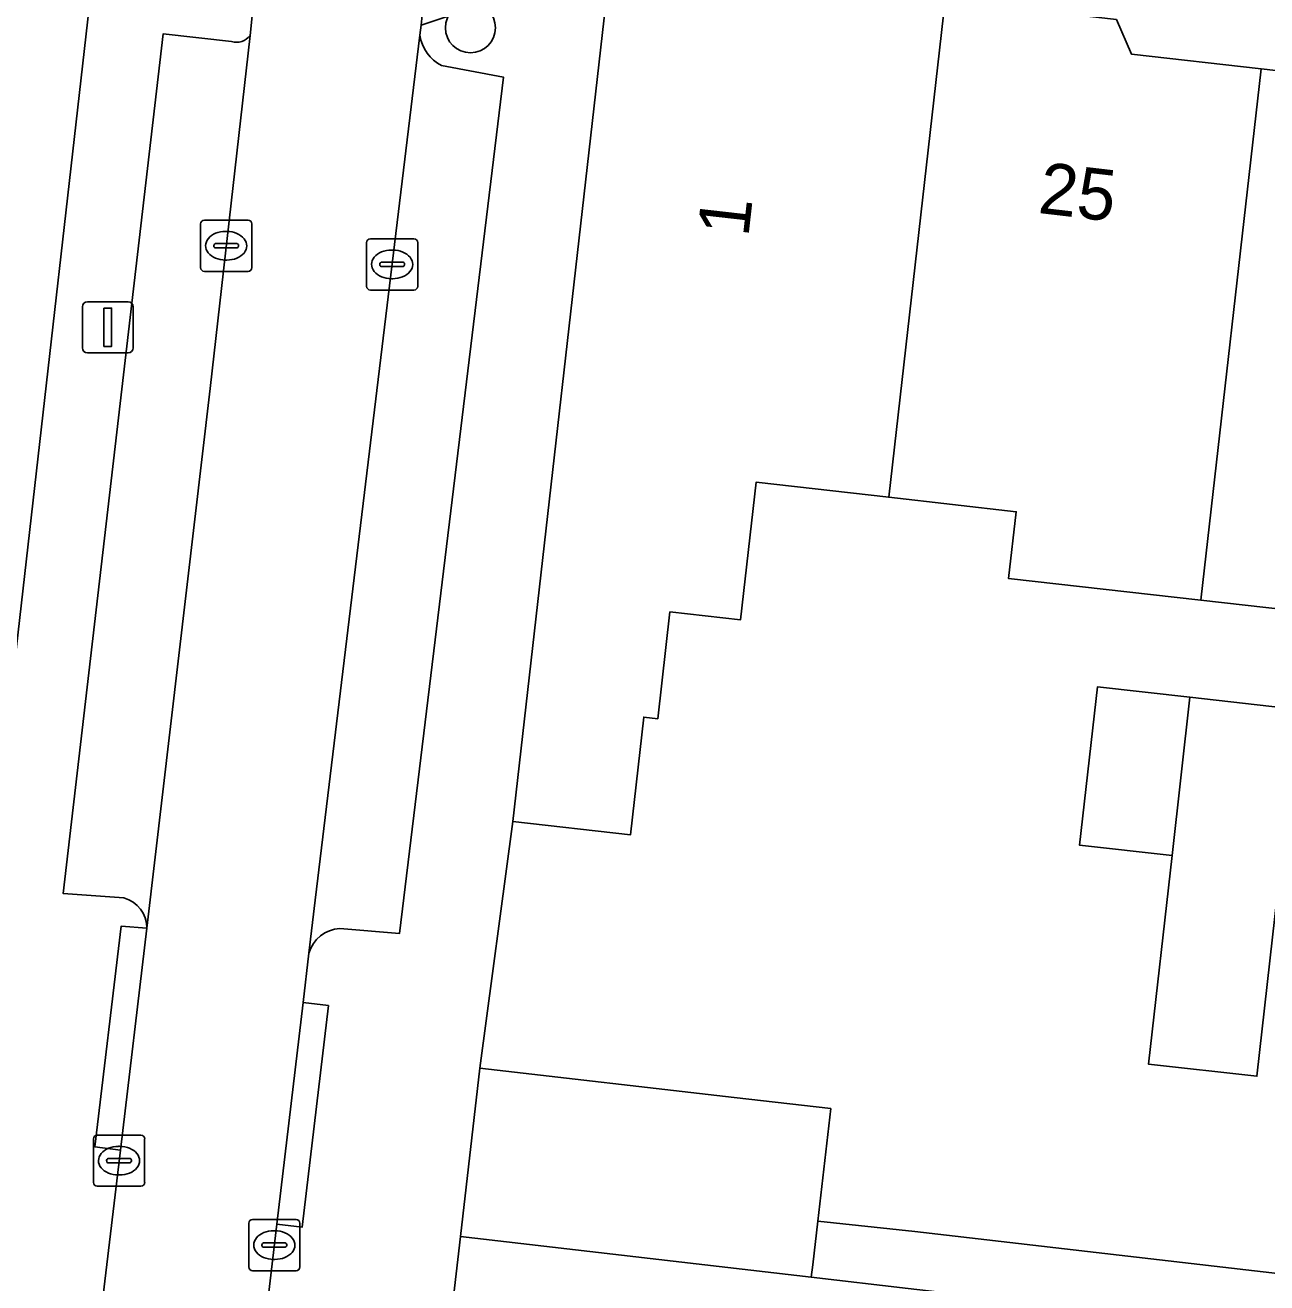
# Model space of a CAD drawing. Extents: x 161692 to 162379, y 380760 to 381678.
# Drawn here: x 162087.29 to 162111.53, y 381116.36 to 381140.92 of the extents above; entities that cross this region are included whole.
import ezdxf

# ---------------------------------------------------------------- set-up
doc = ezdxf.new("R2010")
doc.units = 0
for name, color, linetype in [('IMGEO_Boom', 7, 'Continuous'), ('IMGEO_Erf', 7, 'Continuous'), ('IMGEO_Kolk', 7, 'Continuous'), ('IMGEO_Lichtmast', 7, 'Continuous'), ('IMGEO_Muur', 7, 'Continuous'), ('IMGEO_Pand', 7, 'Continuous'), ('IMGEO_Pand_nummerreeks', 7, 'Continuous'), ('IMGEO_Parkeervlak_open', 7, 'Continuous'), ('IMGEO_Rijbaan_lokaal_open', 7, 'Continuous'), ('IMGEO_Voetpad_open', 7, 'Continuous')]:
    doc.layers.add(name, color=color, linetype=linetype)

msp = doc.modelspace()

# ---------------------------------------------------------------- linework, layer by layer
at = {"layer": 'IMGEO_Boom'}
msp.add_circle((162095.978, 381140.866), 0.489, dxfattribs=at)
at = {"layer": 'IMGEO_Erf'}
msp.add_lwpolyline([(162114.163, 381129.244), (162110.241, 381129.686), (162106.484, 381130.11), (162106.633, 381131.414), (162104.145, 381131.697), (162101.554, 381131.991), (162101.248, 381129.301), (162099.872, 381129.457), (162099.635, 381127.373), (162099.363, 381127.404), (162099.102, 381125.102), (162096.806, 381125.362), (162096.163, 381120.55), (162101.13, 381119.976), (162103.013, 381119.759), (162102.759, 381117.558), (162104.656, 381117.359), (162150.568, 381112.043)], dxfattribs=at)
msp.add_lwpolyline([(162109.675, 381124.698), (162107.87, 381124.902), (162108.218, 381127.994), (162110.026, 381127.79), (162112.139, 381127.552), (162111.332, 381120.389), (162109.214, 381120.628)], close=True, dxfattribs=at)
at = {"layer": 'IMGEO_Kolk'}
for p, q in [((162090.784, 381137.108), (162091.636, 381137.108)), ((162090.709, 381136.182), (162090.709, 381137.034)), ((162091.197, 381136.888), (162091.222, 381136.888)), ((162091.71, 381137.034), (162091.71, 381136.182)), ((162090.968, 381136.602), (162090.968, 381136.614)), ((162091.011, 381136.651), (162091.409, 381136.651)), ((162091.452, 381136.614), (162091.452, 381136.602)), ((162093.949, 381135.818), (162093.949, 381136.67)), ((162094.024, 381136.744), (162094.876, 381136.744)), ((162094.95, 381136.67), (162094.95, 381135.818)), ((162091.406, 381136.565), (162091.008, 381136.565)), ((162091.22, 381136.328), (162091.195, 381136.328)), ((162094.437, 381136.524), (162094.462, 381136.524)), ((162091.636, 381136.108), (162090.784, 381136.108)), ((162094.208, 381136.238), (162094.208, 381136.25)), ((162094.646, 381136.201), (162094.248, 381136.201)), ((162094.251, 381136.287), (162094.649, 381136.287)), ((162094.692, 381136.25), (162094.692, 381136.238)), ((162094.46, 381135.964), (162094.435, 381135.964)), ((162094.876, 381135.744), (162094.024, 381135.744)), ((162088.617, 381118.316), (162088.617, 381119.168)), ((162088.692, 381119.242), (162089.544, 381119.242)), ((162089.618, 381119.168), (162089.618, 381118.316)), ((162089.105, 381119.022), (162089.13, 381119.022)), ((162088.876, 381118.736), (162088.876, 381118.748)), ((162089.314, 381118.699), (162088.916, 381118.699)), ((162088.919, 381118.785), (162089.317, 381118.785)), ((162089.36, 381118.748), (162089.36, 381118.736)), ((162089.128, 381118.462), (162089.103, 381118.462)), ((162089.544, 381118.242), (162088.692, 381118.242)), ((162091.649, 381116.667), (162091.649, 381117.519)), ((162091.724, 381117.593), (162092.576, 381117.593)), ((162092.65, 381117.519), (162092.65, 381116.667)), ((162092.137, 381117.373), (162092.162, 381117.373)), ((162091.908, 381117.087), (162091.908, 381117.099)), ((162092.346, 381117.05), (162091.948, 381117.05)), ((162091.951, 381117.136), (162092.349, 381117.136)), ((162092.392, 381117.099), (162092.392, 381117.087)), ((162092.16, 381116.813), (162092.135, 381116.813)), ((162092.576, 381116.593), (162091.724, 381116.593))]:
    msp.add_line(p, q, dxfattribs=at)
for points in [[(162090.784, 381137.108), (162091.636, 381137.108)], [(162090.709, 381136.182), (162090.709, 381137.034)], [(162091.71, 381137.034), (162091.71, 381136.182)], [(162093.949, 381135.818), (162093.949, 381136.67)], [(162094.024, 381136.744), (162094.876, 381136.744)], [(162094.95, 381136.67), (162094.95, 381135.818)], [(162091.636, 381136.108), (162090.784, 381136.108)], [(162094.876, 381135.744), (162094.024, 381135.744)], [(162088.617, 381118.316), (162088.617, 381119.168)], [(162088.692, 381119.242), (162089.544, 381119.242)], [(162089.618, 381119.168), (162089.618, 381118.316)], [(162089.544, 381118.242), (162088.692, 381118.242)], [(162091.649, 381116.667), (162091.649, 381117.519)], [(162091.724, 381117.593), (162092.576, 381117.593)], [(162092.65, 381117.519), (162092.65, 381116.667)], [(162092.576, 381116.593), (162091.724, 381116.593)]]:
    msp.add_lwpolyline(points, dxfattribs=at)
for centre, radius, start, end in [((162090.786, 381137.032), 0.0765, 91.552, 178.448), ((162090.786, 381137.032), 0.0765, 91.552, 178.448), ((162091.634, 381137.032), 0.0765, 1.552, 88.448), ((162091.634, 381137.032), 0.0765, 1.552, 88.448), ((162091.008, 381136.611), 0.0403, 85.8775, 175.7526), ((162091.005, 381136.601), 0.0366, 178.938, 274.7102), ((162091.409, 381136.608), 0.043, 264.8664, 352.4533), ((162091.413, 381136.613), 0.0386, 1.7309, 96.639), ((162094.026, 381136.668), 0.0765, 91.552, 178.448), ((162094.026, 381136.668), 0.0765, 91.552, 178.448), ((162094.874, 381136.668), 0.0765, 1.552, 88.448), ((162094.874, 381136.668), 0.0765, 1.552, 88.448), ((162090.786, 381136.184), 0.0765, 181.552, 268.448), ((162090.786, 381136.184), 0.0765, 181.552, 268.448), ((162091.634, 381136.184), 0.0765, 271.552, 358.448), ((162091.634, 381136.184), 0.0765, 271.552, 358.448), ((162094.248, 381136.247), 0.0403, 85.8775, 175.7526), ((162094.245, 381136.237), 0.0366, 178.938, 274.7102), ((162094.649, 381136.244), 0.043, 264.8664, 352.4533), ((162094.653, 381136.249), 0.0386, 1.7309, 96.639), ((162094.026, 381135.82), 0.0765, 181.552, 268.448), ((162094.026, 381135.82), 0.0765, 181.552, 268.448), ((162094.874, 381135.82), 0.0765, 271.552, 358.448), ((162094.874, 381135.82), 0.0765, 271.552, 358.448), ((162088.694, 381119.166), 0.0765, 91.552, 178.448), ((162088.694, 381119.166), 0.0765, 91.552, 178.448), ((162089.542, 381119.166), 0.0765, 1.552, 88.448), ((162089.542, 381119.166), 0.0765, 1.552, 88.448), ((162088.916, 381118.745), 0.0403, 85.8775, 175.7526), ((162088.913, 381118.735), 0.0366, 178.938, 274.7102), ((162089.317, 381118.742), 0.043, 264.8664, 352.4533), ((162089.321, 381118.747), 0.0386, 1.7309, 96.639), ((162088.694, 381118.318), 0.0765, 181.552, 268.448), ((162088.694, 381118.318), 0.0765, 181.552, 268.448), ((162089.542, 381118.318), 0.0765, 271.552, 358.448), ((162089.542, 381118.318), 0.0765, 271.552, 358.448), ((162091.726, 381117.517), 0.0765, 91.552, 178.448), ((162091.726, 381117.517), 0.0765, 91.552, 178.448), ((162092.574, 381117.517), 0.0765, 1.552, 88.448), ((162092.574, 381117.517), 0.0765, 1.552, 88.448), ((162091.948, 381117.096), 0.0403, 85.8775, 175.7526), ((162091.945, 381117.086), 0.0366, 178.938, 274.7102), ((162092.349, 381117.093), 0.043, 264.8664, 352.4533), ((162092.353, 381117.098), 0.0386, 1.7309, 96.639), ((162091.726, 381116.669), 0.0765, 181.552, 268.448), ((162091.726, 381116.669), 0.0765, 181.552, 268.448), ((162092.574, 381116.669), 0.0765, 271.552, 358.448), ((162092.574, 381116.669), 0.0765, 271.552, 358.448)]:
    msp.add_arc(centre, radius, start, end, dxfattribs=at)
for centre, major_axis, ratio, start_param, end_param in [((162091.196, 381136.608), (-0.387, 0.002), 0.722429, 4.712389, 7.853982), ((162091.221, 381136.608), (-0.39, 0.002), 0.717154, 1.570796, 4.712389), ((162094.436, 381136.244), (-0.387, 0.002), 0.722429, 4.712389, 7.853982), ((162094.461, 381136.244), (-0.39, 0.002), 0.717154, 1.570796, 4.712389), ((162089.104, 381118.742), (-0.387, 0.002), 0.722429, 4.712389, 7.853982), ((162089.129, 381118.742), (-0.39, 0.002), 0.717154, 1.570796, 4.712389), ((162092.136, 381117.093), (-0.387, 0.002), 0.722429, 4.712389, 7.853982), ((162092.161, 381117.093), (-0.39, 0.002), 0.717154, 1.570796, 4.712389)]:
    msp.add_ellipse(centre, major_axis=major_axis, ratio=ratio, start_param=start_param, end_param=end_param, dxfattribs=at)
at = {"layer": 'IMGEO_Lichtmast'}
for p, q in [((162088.403, 381134.616), (162088.403, 381135.416)), ((162088.403, 381135.416), (162088.403, 381134.616)), ((162088.503, 381135.516), (162089.293, 381135.516)), ((162089.293, 381135.516), (162088.503, 381135.516)), ((162089.393, 381135.416), (162089.393, 381134.616)), ((162089.393, 381134.616), (162089.393, 381135.416)), ((162089.293, 381134.516), (162088.503, 381134.516)), ((162088.503, 381134.516), (162089.293, 381134.516))]:
    msp.add_line(p, q, dxfattribs=at)
msp.add_lwpolyline([(162088.823, 381135.391), (162088.973, 381135.391), (162088.973, 381134.641), (162088.823, 381134.641), (162088.823, 381135.391)], dxfattribs=at)
for centre, start, end in [((162088.503, 381135.416), 90, 180), ((162088.503, 381135.416), 90, 180), ((162089.293, 381135.416), 0, 90), ((162089.293, 381135.416), 360, 90), ((162088.503, 381134.616), 180, 270), ((162088.503, 381134.616), 180, 270), ((162089.293, 381134.616), 270, 0), ((162089.293, 381134.616), 270, 0)]:
    msp.add_arc(centre, 0.1, start, end, dxfattribs=at)
at = {"layer": 'IMGEO_Muur'}
msp.add_lwpolyline([(162096.806, 381125.362), (162096.163, 381120.55)], dxfattribs=at)
at = {"layer": 'IMGEO_Pand'}
for points in [[(162081.935, 381144.049), (162080.779, 381134.286), (162080.655, 381133.357), (162083.55, 381133.042), (162083.371, 381131.369), (162084.693, 381131.219), (162084.45, 381129.08), (162087.113, 381128.778), (162088.76, 381143.274)], [(162105.246, 381141.408), (162098.713, 381142.15), (162096.806, 381125.362), (162099.102, 381125.102), (162099.363, 381127.404), (162099.635, 381127.373), (162099.872, 381129.457), (162101.248, 381129.301), (162101.554, 381131.991), (162104.145, 381131.697)], [(162105.246, 381141.408), (162104.145, 381131.697), (162106.633, 381131.414), (162106.484, 381130.11), (162110.241, 381129.686), (162111.418, 381140.063), (162108.883, 381140.351), (162108.589, 381141.028)], [(162117.619, 381139.339), (162117.069, 381139.402), (162116.786, 381140.052), (162114.638, 381140.296), (162114.23, 381139.744), (162111.418, 381140.063), (162110.241, 381129.686), (162114.163, 381129.244), (162114.308, 381130.511), (162116.589, 381130.252)], [(162110.026, 381127.79), (162108.218, 381127.994), (162107.87, 381124.902), (162109.675, 381124.698)], [(162110.026, 381127.79), (162109.675, 381124.698), (162109.214, 381120.628), (162111.332, 381120.389), (162112.139, 381127.552)], [(162103.013, 381119.759), (162101.13, 381119.976), (162096.163, 381120.55), (162095.782, 381117.258), (162102.633, 381116.465), (162102.661, 381116.71), (162102.759, 381117.558)], [(162104.527, 381116.246), (162102.633, 381116.465), (162095.782, 381117.258), (162095.141, 381111.709), (162109.163, 381110.087), (162109.187, 381110.297), (162110.97, 381110.09), (162111.216, 381112.206), (162109.432, 381112.412), (162107.784, 381112.603), (162107.839, 381113.073), (162108.158, 381115.826)]]:
    msp.add_lwpolyline(points, close=True, dxfattribs=at)
at = {"layer": 'IMGEO_Parkeervlak_open'}
for points in [[(162091.313, 381140.596), (162089.979, 381140.744), (162088.03, 381123.957), (162089.211, 381123.872)], [(162089.66, 381123.283), (162090.897, 381133.818), (162091.675, 381140.712)], [(162094.991, 381140.718), (162092.948, 381123.832), (162092.825, 381122.794)], [(162093.427, 381123.276), (162094.596, 381123.179), (162096.621, 381139.903), (162095.414, 381140.127)]]:
    msp.add_lwpolyline(points, dxfattribs=at)
for centre, radius, start, end in [((162091.411, 381140.913), 0.332, 252.8518, 322.6835), ((162095.776, 381140.833), 0.793, 188.3323, 242.853), ((162089.054, 381123.287), 0.606, 359.6524, 74.9848), ((162093.465, 381122.611), 0.666, 93.2812, 164.0848)]:
    msp.add_arc(centre, radius, start, end, dxfattribs=at)
at = {"layer": 'IMGEO_Rijbaan_lokaal_open'}
for points in [[(162091.718, 381141.095), (162091.675, 381140.712), (162090.897, 381133.818), (162089.66, 381123.283), (162089.144, 381118.949), (162088.062, 381109.853), (162087.354, 381103.53), (162086.495, 381095.852), (162085.982, 381091.591), (162089.124, 381091.282), (162089.351, 381093.214), (162091.375, 381110.553), (162091.779, 381113.963), (162092.199, 381117.505), (162092.711, 381121.831), (162092.825, 381122.794), (162092.948, 381123.832), (162094.991, 381140.718)], [(162094.991, 381140.718), (162095.015, 381140.916)]]:
    msp.add_lwpolyline(points, dxfattribs=at)
msp.add_arc((162098.872, 381140.649), 3.866, 83.6337, 176.0458, dxfattribs=at)
at = {"layer": 'IMGEO_Voetpad_open'}
for points in [[(162091.779, 381143.228), (162088.76, 381143.274), (162087.113, 381128.778), (162086.463, 381123.177), (162086.034, 381119.469), (162085.911, 381118.471), (162085.144, 381111.839), (162084.533, 381106.562), (162084.352, 381105.057), (162081.406, 381080.534), (162080.783, 381075.07), (162080.609, 381073.546), (162073.358, 381009.985), (162072.098, 381000), (162069.905, 380982.626), (162069.864, 380982.299), (162069.64, 380980.521), (162068.692, 380973.013), (162065.061, 380951.346)], [(162089.842, 381066.266), (162090.553, 381072.412), (162090.77, 381073.897), (162091.404, 381079.381), (162091.965, 381084.236), (162092.588, 381089.623), (162093.223, 381095.12), (162093.332, 381096.064), (162093.949, 381101.4), (162094.532, 381106.442), (162095.141, 381111.709), (162095.782, 381117.258), (162096.163, 381120.55), (162096.806, 381125.362), (162098.713, 381142.15), (162095.015, 381140.916), (162094.991, 381140.718)], [(162095.015, 381140.916), (162098.713, 381142.15), (162105.246, 381141.408), (162108.589, 381141.028), (162108.883, 381140.351), (162111.418, 381140.063), (162114.23, 381139.744)], [(162091.675, 381140.712), (162091.718, 381141.095)], [(162089.211, 381123.872), (162088.03, 381123.957), (162089.979, 381140.744), (162091.313, 381140.596)], [(162095.414, 381140.127), (162096.621, 381139.903), (162094.596, 381123.179), (162093.427, 381123.276)], [(162087.354, 381103.53), (162088.062, 381109.853), (162089.144, 381118.949), (162088.648, 381119.009), (162089.161, 381123.322), (162089.66, 381123.283)], [(162092.825, 381122.794), (162092.711, 381121.831), (162093.207, 381121.77), (162092.695, 381117.444), (162092.199, 381117.505), (162091.779, 381113.963), (162092.255, 381113.359), (162093.423, 381113.312), (162090.97, 381091.636), (162089.687, 381091.746), (162089.124, 381091.282), (162088.771, 381088.276), (162089.282, 381087.721), (162090.425, 381087.623), (162088.612, 381071.877), (162087.456, 381072.013)]]:
    msp.add_lwpolyline(points, dxfattribs=at)
for points in [[(162089.66, 381123.283), (162089.161, 381123.322), (162088.648, 381119.009), (162089.144, 381118.949)], [(162092.711, 381121.831), (162092.199, 381117.505), (162092.695, 381117.444), (162093.207, 381121.77)], [(162104.656, 381117.359), (162102.759, 381117.558), (162102.661, 381116.71), (162102.633, 381116.465), (162104.527, 381116.246), (162108.158, 381115.826), (162123.177, 381114.087), (162150.439, 381110.931), (162150.568, 381112.043)]]:
    msp.add_lwpolyline(points, close=True, dxfattribs=at)
for centre, radius, start, end in [((162098.872, 381140.649), 3.866, 83.6337, 176.0458), ((162091.411, 381140.913), 0.332, 252.8518, 322.6835), ((162095.776, 381140.833), 0.793, 188.3323, 242.853), ((162089.054, 381123.287), 0.606, 359.6524, 74.9848), ((162093.465, 381122.611), 0.666, 93.2812, 164.0848)]:
    msp.add_arc(centre, radius, start, end, dxfattribs=at)

# ---------------------------------------------------------------- texts
at = {"layer": 'IMGEO_Pand_nummerreeks'}
for s, rotation, p in [('25', 353.3338, (162107.041, 381137.251)), ('1', 83.5194, (162101.403, 381136.763))]:
    msp.add_text(s, height=1, rotation=rotation, dxfattribs=at).set_placement(p)

doc.saveas('drawing.dxf')
